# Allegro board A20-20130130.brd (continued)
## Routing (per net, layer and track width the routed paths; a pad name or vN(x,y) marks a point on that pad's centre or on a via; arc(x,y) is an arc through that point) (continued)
SDQ25: length 25.3
  TOP w0.102: U5.C8 84.31,60.26 85.41,60.26 85.51,60.16 85.51,59.07 85.66,58.92 85.88,58.92 86.1,59.15 86.1,60.2 85.9,60.4 85.9,60.61 86.1,60.81 86.1,63.32 86.38,63.59 86.38,63.96 86.14,64.2 85.39,64.2 85.31,64.28 85.31,64.41 85.48,64.57 86.05,64.57 86.11,64.63 86.11,64.99 86.23,65.11 86.4,65.11 86.53,64.98 86.53,64.43 86.61,64.36 86.78,64.36 86.89,64.46 86.89,65.01 86.98,65.11 87.2,65.11 87.31,65 87.31,64.52 87.38,64.44 87.57,64.44 87.72,64.58 87.72,64.99 87.84,65.11 91.04,65.11 95.05,69.11 U1.L1
SDQ26: length 25
  TOP w0.102: U5.D2 78.84,59.06 78.69,59.2 78.69,60.13 78.83,60.27 79.25,60.27 79.25,60.27 79.27,60.27 79.49,60.48 79.49,61.81 79.57,61.9 79.88,61.9 79.97,61.99 79.97,62.09 79.88,62.18 79.47,62.18 79.42,62.23 79.42,62.23 79.42,62.42 79.51,62.51 79.89,62.51 79.97,62.6 79.97,62.7 79.72,62.95 79.72,63.12 79.84,63.25 80,63.25 80.07,63.19 80.23,63.19 80.36,63.31 80.36,63.47 80.29,63.54 80.29,63.7 80.42,63.83 80.58,63.83 80.64,63.76 80.81,63.76 80.93,63.89 80.93,64.05 80.87,64.11 80.87,64.28 81,64.4 81.16,64.4 81.22,64.34 81.39,64.34 81.51,64.47 81.51,64.63 81.45,64.69 81.45,64.86 81.57,64.98 81.74,64.98 81.8,64.92 81.97,64.92 82.09,65.04 82.09,65.21 82.03,65.27 82.03,65.44 82.15,65.56 82.32,65.56 82.38,65.5 82.55,65.5 82.67,65.62 82.67,65.79 82.61,65.85 82.61,66.02 82.73,66.14 82.9,66.14 82.96,66.08 83.13,66.08 83.25,66.2 83.25,66.37 83.19,66.43 83.19,66.6 83.31,66.72 83.48,66.72 83.54,66.66 83.71,66.66 83.83,66.78 83.83,66.95 83.77,67.01 83.77,67.18 83.89,67.3 84.06,67.3 84.12,67.24 84.29,67.24 84.84,67.79 90.72,67.79 91.52,68.6 91.52,68.61 92.65,69.74 U1.H1
SDQ27: length 25.5
  TOP w0.102: U5.C7 83.14,59.82 83.39,59.82 83.49,59.93 83.49,61.74 84.02,62.27 85.73,62.27 85.81,62.34 85.81,62.54 85.73,62.63 84.57,62.63 84.5,62.7 84.5,62.87 84.58,62.95 85.61,62.95 85.69,63.03 85.69,63.19 85.62,63.26 84.96,63.26 84.86,63.36 84.86,63.51 84.98,63.62 85.92,63.62 85.99,63.7 85.99,63.88 85.94,63.93 85.03,63.93 84.95,64.01 84.95,64.46 85.96,65.47 90.97,65.47 94.65,69.14 94.65,70.48 U1.K2
SDQ28: length 25.2
  TOP w0.102: U1.L2 95.45,70.48 95.45,69.08 91.17,64.8 89.5,64.8 89.08,64.37 88.9,64.37 88.51,64.76 88.41,64.76 88.24,64.59 88.24,64.47 88.37,64.33 88.37,64.33 88.62,64.08 88.62,63.92 88.14,63.43 87.97,63.43 87.34,64.06 87.17,64.06 87.05,63.94 87.05,63.77 87.68,63.14 87.68,62.97 87.51,62.8 87.34,62.8 86.8,63.35 86.72,63.35 86.63,63.26 86.63,62.94 86.71,62.86 86.71,59.14 86.05,58.48 85.64,58.48 85.46,58.66 83.48,58.66 83.16,58.34 83.1,58.28 U5.E7
  TOP w0.127: 83.1,58.28 83.08,58.26 ; 95.05,70.88 U1.L2
SDQ29: length 25.1
  TOP w0.102: U1.G2 92.25,70.48 92.25,69.75 91.23,68.72 91.22,68.72 90.59,68.1 84.25,68.1 84.18,68.02 84.18,67.81 84.02,67.65 83.81,67.65 79.24,63.08 79.24,62.93 79.31,62.85 79.31,62.72 78.89,62.3 78.54,62.3 77.5,61.26 77.5,58.83 77.67,58.66 79.24,58.66 79.25,58.65 79.26,58.65 79.65,58.26 79.73,58.26 79.73,58.25 U5.E3
SDQ30: length 25
  TOP w0.102: U1.M1 95.85,69.03 91.32,64.49 89.72,64.49 87.04,61.81 87.04,58.93 87.64,58.34 87.64,57.75 87.51,57.62 86.85,57.62 86.72,57.76 86.72,58.22 86.64,58.3 86.44,58.3 86.37,58.22 86.37,57.9 86.24,57.78 85.82,57.78 85.75,57.7 85.75,57.47 85.83,57.38 86.46,57.38 86.54,57.3 86.54,56.87 86.46,56.79 86.04,56.79 85.69,57.14 85.34,57.14 85.23,57.25 85.23,57.51 85.11,57.62 85.09,57.62 84.85,57.86 84.29,57.86 U5.E8
SDQ31: length 25.1
  TOP w0.102: U1.H2 92.65,70.63 93.04,70.24 93.04,70.23 93.05,70.22 93.05,69.7 90.84,67.49 90.84,67.49 90.8,67.45 85.01,67.45 82.76,65.2 82.76,64.99 82.95,64.8 82.95,64.71 82.84,64.6 82.69,64.6 82.68,64.62 82.68,64.62 82.53,64.77 82.32,64.77 82.21,64.66 82.21,64.49 82.93,63.78 82.93,63.62 82.81,63.5 82.63,63.5 82.32,63.8 81.92,64.2 81.75,64.2 81.64,64.08 81.64,63.93 82.01,63.55 82.01,63.43 81.94,63.36 81.6,63.36 81.38,63.58 81.14,63.58 80.92,63.37 80.92,63.25 80.71,63.03 80.59,63.03 80.31,62.75 80.31,61.25 80.85,60.71 80.85,60.7 81.01,60.55 81.01,60.39 80.81,60.19 80.59,60.19 80.5,60.29 80.5,60.29 80.25,60.54 80.02,60.54 U5.B3
SDQM0: length 26.8
  TOP w0.102: U1.AC6 104.65,74.08 105.28,74.08 106.5,72.86 110.54,72.86 119.55,63.84 119.55,58.86 119.63,58.79 119.88,58.79 120.08,58.99 120.08,60.54 120.17,60.62 120.51,60.62 U2.B7
SDQM1: length 17.6
  TOP w0.102: v1(105.15,62.69) 105.21,62.75 105.35,62.75 105.77,63.17 105.77,64.7 101.83,68.63 101.83,69.22 101.48,69.57 101.48,70.05 U1.W1 ; U3.B7 109.9,60.69 109.87,60.69 109.55,61.01 109.55,62.43 109.97,62.84 v1(109.97,63.25)
  BOTTOM w0.102: v1(105.15,62.69) 105.21,62.76 106.26,62.76 106.76,63.25 v1(109.97,63.25)
SDQM2: length 15.2
  TOP w0.102: U4.B7 93.29,60.77 93.29,61 93.14,61.15 92.49,61.15 92.27,61.37 92.27,61.5 92.36,61.6 92.95,61.6 93.04,61.69 93.04,61.79 92.93,61.9 92.93,62.1 93.11,62.29 93.11,62.29 94.96,64.14 94.96,64.26 96.07,65.36 96.91,65.36 97.03,65.48 97.03,66.32 98.65,67.95 98.65,68.52 98.53,68.64 98.53,68.93 98.65,69.05 98.65,69.26 98.54,69.36 98.54,69.63 98.65,69.73 98.65,70.81 98.6,70.87 98.26,70.87 U1.R2
SDQM3: length 30
  TOP w0.102: U1.G1 91.85,69.78 90.47,68.4 84.11,68.4 77.19,61.48 77.19,58 78.14,57.06 80.07,57.06 82.17,59.16 82.17,59.55 83.08,60.46 83.08,60.64 U5.B7
SDQS0: length 28.2
  TOP w0.114: U2.C3 117.41,59.92 117.78,59.92 117.83,59.87 117.83,59.51 118.15,59.19 118.76,59.19 119.13,59.56 119.13,62.77 117.94,63.96 117.94,64.36 117.46,64.83 116.9,64.83 116.72,65.01 116.72,65.57 116.36,65.93 115.8,65.93 115.63,66.11 115.63,66.66 115.27,67.03 114.71,67.03 114.53,67.2 114.53,67.76 114.17,68.12 113.61,68.12 113.43,68.3 113.43,68.86 113.07,69.22 112.51,69.22 112.34,69.4 112.34,69.95 111.98,70.31 111.42,70.31 111.24,70.49 111.24,71.05 110.88,71.41 110.32,71.41 110.15,71.59 110.15,72.06 109.84,72.36 106.55,72.36 105.32,73.59 104.88,73.59 104.81,73.66 104.27,73.66 U1.AB6
SDQS1: length 18.6
  TOP w0.114: U3.C3 106.76,59.82 106.76,59.67 106.35,59.25 106.35,58.87 106.58,58.64 106.92,58.64 107.71,59.43 107.71,59.48 108.26,60.04 108.26,63.26 108.38,63.38 109.49,63.38 110.08,63.97 110.08,64.8 106.53,68.35 105.19,68.35 103.99,69.55 103.85,69.69 U1.AB1
SDQS2: length 17.7
  TOP w0.114: U4.C3 90.17,59.89 90.17,59.79 89.76,59.38 89.76,59.25 89.76,59.25 89.76,58.95 90.03,58.69 91.55,58.69 91.92,59.06 91.92,59.68 91.24,60.36 91.24,61.09 94.61,64.45 94.61,64.72 98.18,68.29 98.18,70 U1.R1
SDQS3: length 27.6
  TOP w0.114: U1.K1 94.25,69.42 94.06,69.23 94.03,69.23 90.81,66 90.16,66 89.77,66.38 89.35,66.38 89.22,66.25 89.22,66.09 88.94,65.81 88.36,65.81 88.09,66.07 88.09,66.36 87.99,66.46 87.48,66.46 87.36,66.34 87.36,66.19 87,65.84 86.4,65.84 85.93,66.31 85.62,66.31 85.42,66.11 85.42,65.63 85.04,65.25 84.63,65.25 84.45,65.07 84.45,63.36 83.39,62.29 81.55,62.29 81.35,62.09 81.35,61.73 81.55,61.54 82.4,61.54 82.69,61.24 82.69,60.63 81.51,59.43 81.51,59.2 80.98,58.67 79.66,58.67 79.48,58.85 79.48,59.31 79.88,59.71 ; 79.88,59.71 79.9,59.73 U5.C3 ; 79.88,59.71 79.88,59.86
SDQSB0: length 28
  TOP w0.114: U2.D3 117.25,58.96 116.99,58.96 116.91,59.04 116.91,60.01 117.13,60.23 117.92,60.23 118.15,60 118.15,59.64 118.28,59.51 118.63,59.51 118.81,59.69 118.81,62.64 117.62,63.83 117.62,64.22 117.33,64.52 116.77,64.52 116.41,64.88 116.41,65.44 116.23,65.61 115.67,65.61 115.31,65.98 115.31,66.54 115.13,66.71 114.57,66.71 114.21,67.07 114.21,67.63 114.04,67.81 113.48,67.81 113.12,68.17 113.12,68.73 112.94,68.9 112.38,68.9 112.02,69.26 112.02,69.82 111.85,70 111.29,70 110.92,70.36 110.92,70.92 110.75,71.09 110.19,71.09 109.83,71.46 109.83,71.93 109.71,72.05 106.42,72.05 105.19,73.28 U1.AC5
SDQSB1: length 18.6
  TOP w0.114: U3.D3 106.76,59.04 107.14,59.43 107.14,59.43 107.26,59.55 107.26,59.94 107.38,60.06 107.51,60.06 107.59,59.98 107.76,59.98 107.95,60.17 107.95,63.39 108.28,63.73 109.39,63.73 109.76,64.1 109.76,64.67 106.39,68.04 106.06,68.04 105.89,67.87 105.89,67.64 105.79,67.54 105.45,67.54 105.4,67.58 105.4,67.91 105.28,68.04 105.04,68.04 104.5,68.57 103.47,69.61 103.47,70.24 103.47,70.24 103.47,70.78 103.37,70.88 103.06,70.88 U1.AA2
SDQSB2: length 17.6
  TOP w0.114: U1.P2 97.68,70.65 97.87,70.65 97.98,70.53 97.98,70.39 97.86,70.27 97.86,68.43 94.29,64.86 94.29,64.58 90.93,61.22 90.93,60.23 91.61,59.55 91.61,59.19 91.42,59 91.01,59 90.9,59.11 90.9,59.55 90.77,59.68 90.52,59.68 90.18,59.34 U4.D3
SDQSB3: length 27.5
  TOP w0.114: U1.J2 93.45,71.12 93.46,71.13 93.36,71.23 93.24,71.23 93.11,71.11 93.11,70.55 93.19,70.47 93.61,70.47 93.82,70.26 93.82,70.25 93.84,70.24 93.84,69.48 90.67,66.32 90.29,66.32 89.92,66.69 89.21,66.69 88.91,66.38 88.91,66.22 88.81,66.12 88.49,66.12 88.41,66.21 88.41,66.49 88.12,66.78 87.34,66.78 87.04,66.48 87.04,66.33 86.87,66.16 86.53,66.16 86.06,66.63 85.48,66.63 85.1,66.24 85.1,65.76 84.91,65.57 84.5,65.57 84.14,65.21 84.14,63.49 83.26,62.61 81.42,62.61 81.03,62.22 81.03,61.6 81.41,61.22 82.26,61.22 82.38,61.1 82.38,60.77 81.19,59.57 81.19,59.33 80.85,58.99 79.97,58.99 U5.D3
SODT: length 72.3
  TOP w0.102: v1(102.76,64.56) 101.43,63.23 101.43,56.01 v1(101.53,55.91) ; 105.16,56.62 U3.G1 ; 78.11,56.49 78.28,56.65 U5.G1 ; U4.G1 88.57,56.69
  TOP w0.127: U1.AA5 v1(103.45,72.88) ; v1(77.88,56.26) 78.11,56.49
  TOP w0.152: 78.11,56.49 78.28,56.66 ; 88.57,56.69 88.48,56.69 88.26,56.47 v1(88.05,56.47) ; 105.16,56.62 105.04,56.5 104.64,56.5 104.57,56.57 104.57,56.57 v1(104.56,56.58) ; 115.69,56.62 115.7,56.62 115.32,56.24 v1(115.31,56.24) 115.69,56.62
  BOTTOM w0.102: v1(103.45,72.88) 103.72,72.61 103.72,72.54 104.52,71.75 104.52,70.46 106.19,68.79 106.19,63.48 105.79,63.09 104.79,63.09 103.32,64.56 v1(102.76,64.56) ; v1(115.31,56.24) 115.1,56.24 115.04,56.17 113.58,56.17 112.84,55.44 112.84,54.93 112.13,54.22 111.03,54.22 109.9,55.34 108.87,55.34 107.82,56.4 107.58,56.63 105.39,56.63 105.39,56.63 104.62,56.63 104.57,56.58 v1(104.56,56.58) 104.18,56.96 102.26,56.96 101.57,56.27 101.57,55.95 v1(101.53,55.91) 101.53,55.68 100.68,54.84 100.68,54.36 100.29,53.98 92.97,53.98 90.25,56.69 89.58,56.69 89.46,56.81 88.51,56.81 88.17,56.47 v1(88.05,56.47) 87.98,56.4 86.55,56.4 85.95,55.79 85.95,55.56 85.37,54.98 82.23,54.98 80.54,56.68 78.28,56.68 77.88,56.27 v1(77.88,56.26)
SRAS: length 65.4
  TOP w0.102: v1(106.37,57.04) 106.75,57.42 U3.F3 ; v1(80.28,57.86) 80.1,57.68 80.1,57.66 U5.F3 ; U4.F3 90.18,57.46 90.17,57.45 ; v1(117.92,56.44) 117.92,56.81 U2.F3 ; v1(100.26,54.54) 100.26,54.92 100.21,54.97 100.21,63.36 99.53,64.03 v1(99.53,66.13)
  TOP w0.127: U1.T4 v1(99.45,72.08)
  TOP w0.152: v1(89.81,57.09) 90.17,57.45 90.17,57.49
  BOTTOM w0.102: v1(99.45,72.08) 99.06,71.68 99.06,69.49 99.52,69.03 99.52,66.54 99.59,66.48 99.59,66.15 99.56,66.13 v1(99.53,66.13) ; v1(106.37,57.04) 106.34,57.06 ; 106.34,57.06 104.58,57.06 104.33,57.31 102.14,57.31 100.27,55.44 100.27,54.55 v1(100.26,54.54) 100,54.28 93.1,54.28 90.3,57.09 v1(89.81,57.09) 89.61,57.09 89.59,57.11 88.38,57.11 88.12,56.85 87.87,56.85 87.75,56.73 86.43,56.73 85.59,55.89 82.25,55.89 v1(80.28,57.86) ; 106.34,57.06 107.65,57.06 109.01,55.69 110.11,55.69 110.77,55.03 112.01,55.03 112.44,55.46 113.6,56.62 117.74,56.62 v1(117.92,56.44)
SRST: length 105.1
  TOP w0.102: U3.N2 105.96,51.4 105.96,51.4 105.96,50.83 105.88,50.75 105.88,47.37 v1(107.14,46.12) ; U2.N2 116.51,50.36 116.66,50.21 116.66,48.21 116.05,47.6 115.52,47.6 114.79,46.87 114.79,46.81 114.79,46.8 114.79,46.48 114.79,46.48 v1(114.79,46.03) ; v1(82.69,47.38) 82.31,47.38 78.82,50.87 78.82,51.58 U5.N2 ; U4.N2 89.38,51.5 89.37,51.5 89.37,47.84 89.37,47.83 v1(89.37,46.24)
  TOP w0.127: U1.AA6 v1(103.45,73.68)
  BOTTOM w0.102: v1(82.69,47.38) 83.93,46.15 88.91,46.15 88.99,46.24 v1(89.37,46.24) 90.44,45.17 106.23,45.17 107.14,46.08 v1(107.14,46.12) 114.71,46.12 v1(114.79,46.03) 114.88,45.94 118.19,45.94 123.08,50.84 123.08,56.08 116.21,62.96 116.21,62.97 115.34,63.84 107.82,63.84 106.98,64.68 106.98,68.71 104.94,70.75 104.94,71.8 103.93,72.81 103.93,73.2 v1(103.45,73.68)
  BOTTOM w0.152: 82.67,47.38 v1(82.69,47.38)
SWE: length 66.2
  TOP w0.102: v1(89.77,55.49) 90.17,55.89 U4.H3 ; v1(79.48,55.46) 79.88,55.85 U5.H3 ; U3.H3 106.76,55.82 v1(106.36,55.42) ; v1(100.84,52.92) 100.68,53.08 100.68,54.87 100.51,55.04 100.51,63.52 99.94,64.09 v1(99.94,66.71) ; v1(116.9,55.42) 117.3,55.82 U2.H3
  TOP w0.127: U1.T3 v1(99.45,71.28)
  BOTTOM w0.102: v1(99.94,66.71) 99.89,66.76 99.89,69.35 99.45,69.79 v1(99.45,71.28) ; v1(116.9,55.42) 116.51,55.03 115.87,55.03 115.66,55.23 114.48,55.23 114.47,55.22 114.43,55.22 112.51,53.3 110.49,53.3 109.45,54.34 108.48,54.34 107.43,55.38 106.4,55.38 v1(106.36,55.42) 106.15,55.42 105.84,55.11 105.71,55.11 105.65,55.04 105.22,55.04 104.67,55.59 104.46,55.59 103.85,54.97 103.49,54.97 101.44,52.92 v1(100.84,52.92) 100.77,52.85 96.23,52.85 95.76,52.37 94.22,52.37 93.87,52.72 92.88,52.72 90.11,55.49 v1(89.77,55.49) 89.56,55.49 89.19,55.12 88.55,55.12 88.19,55.48 87.36,55.48 86.86,54.98 86.86,54.92 85.36,53.43 83.86,53.43 83.28,54.01 81.73,54.01 80.28,55.46 v1(79.48,55.46)
TP-INT: length 2.8
  TOP w0.102: U1.D3 v1(89.08,71.3)
  BOTTOM w0.102: 87.02,71.72 88.67,71.72 89.08,71.31 v1(89.08,71.3)
TP-WAKEUP: length 12.7
  TOP w0.102: 79.08,85.84 79.08,84.59 85.2,78.46 87.47,78.46 U1.B11
TVDACVCC: length 0.5
  TOP w0.102: U1.W15 v1(101.83,81.65)
TVIN0: length 4.1
  TOP w0.102: U1.AC18 108.8,83.68
TVIN1: length 5.1
  TOP w0.102: 108.8,84.06 104.23,84.06 U1.AB18
TVIN2: length 1.5
  TOP w0.102: U1.AA17 v1(103.43,83.25)
  BOTTOM w0.102: v1(103.43,83.25) 104.42,83.25
TVIN3: length 3.6
  TOP w0.102: U1.Y17 v1(102.63,83.25)
  BOTTOM w0.102: 105.51,82.83 103.03,82.83 102.63,83.24 v1(102.63,83.25)
TWI0-SCK: length 8.4
  TOP w0.102: 81.89,86.83 81.89,85.22 85.83,81.28 U1.A15
TWI0-SDA: length 8.7
  TOP w0.102: 82.27,86.83 82.27,85.37 85.98,81.66 87.47,81.66 U1.B15
TWI1-SCK: length 12.5
  TOP w0.102: 77.48,82.68 84.49,75.68 U1.A8
TWI1-SDA: length 13.2
  TOP w0.102: U1.B8 87.47,76.06 84.58,76.06 77.65,82.98
TWI2-SCK: length 2.2
  TOP w0.102: U1.C8 v1(88.28,75.3)
  BOTTOM w0.102: v1(88.28,75.3) 86.62,75.3
TWI2-SDA: length 2.2
  TOP w0.102: U1.C7 v1(88.28,74.5)
  BOTTOM w0.102: v1(88.28,74.5) 86.62,74.5
TWI3-SCK: length 3.5
  TOP w0.102: U1.A20 86.77,85.28 85.52,86.53 85.52,88.02
TWI3-SDA: length 7.1
  TOP w0.102: 85.82,89.72 85.82,86.73 86.89,85.66 87.47,85.66 U1.B20
  TOP w0.127: 85.82,91.17 85.82,89.72
TWI4-SCK: length 4.5
  TOP w0.102: 84.81,87.74 84.81,86.26 86.59,84.48 U1.A19
TWI4-SDA: length 5.1
  TOP w0.102: U1.B19 87.45,84.88 86.65,84.88 85.16,86.38 85.16,87.97
UART0-RX: length 13.6
  TOP w0.102: 77.34,82.38 84.46,75.26 87.47,75.26 U1.B7
UART0-TX: length 11.3
  TOP w0.102: 78.3,80.94 84.37,74.88 U1.A7
UBOOT: length 0.5
  TOP w0.102: U1.W8 v1(101.83,75.3)
ULVDD: length 0.5
  TOP w0.254: U1.K16 v1(93.88,82.45)
USB0-DRV: length 2.2
  TOP w0.102: U1.C12 v1(88.28,78.5)
  BOTTOM w0.102: v1(88.28,78.5) 86.62,78.5
USB0-IDDET: length 12.9
  TOP w0.102: 77.75,80.08 84.16,73.67 87.45,73.67 U1.B5
USB0-VBUSDET: length 2.2
  TOP w0.102: U1.C5 v1(88.28,72.9)
  BOTTOM w0.102: v1(88.28,72.9) 86.62,72.9
USB1-DRV: length 11.3
  TOP w0.102: 78.16,78.27 83.95,72.48 U1.A4
USB2-DRV: length 10.9
  TOP w0.102: 78.48,78.86 84.07,73.28 U1.A5
USB-ICTRL: length 0.5
  TOP w0.102: U1.G19 v1(91.48,84.85)
UVCC: length 1.1
  TOP w0.254: U1.L16 v1(94.68,82.45) ; U1.L15 v1(94.68,81.65)
VGA-B: length 5.1
  TOP w0.102: 108.8,82.46 104.23,82.46 U1.AB16
VGA-G: length 4.1
  TOP w0.102: U1.AC16 108.8,82.08
VGA-R: length 4.1
  TOP w0.102: U1.AC17 108.8,82.88
VMIC: length 1.6
  TOP w0.102: U1.AA21 v1(103.43,86.45)
  BOTTOM w0.102: v1(103.43,86.45) 104.53,86.45
VRA1: length 7.2
  TOP w0.102: U1.W20 v1(101.83,85.65)
  BOTTOM w0.102: 103.2,89.72 103.2,88.34 102.21,87.35 102.21,85.91 101.96,85.65 v1(101.83,85.65)
  BOTTOM w0.254: 103.2,89.72 103.2,91.66
VRA2: length 6.4
  TOP w0.102: U1.V20 v1(101.03,85.65)
  BOTTOM w0.102: v1(101.03,85.65) 101.04,85.65 101.45,86.06 101.45,88.21 101.88,88.65 101.88,89.72
  BOTTOM w0.254: 101.88,89.72 101.88,91.12
VRN-TVIN: length 2.8
  TOP w0.102: U1.Y16 v1(102.63,82.45)
  BOTTOM w0.102: v1(102.63,82.45) 102.63,82.44 103.04,82.03 104.69,82.03
VRP: length 6.1
  TOP w0.102: U1.W21 v1(101.83,86.45)
  BOTTOM w0.102: 101.83,87.8 v1(101.83,86.45)
  BOTTOM w0.254: 101.83,87.8 102.67,88.64 102.67,91.66
VRP-TVIN: length 1.5
  TOP w0.102: U1.AA16 v1(103.43,82.45)
  BOTTOM w0.102: v1(103.43,82.45) 104.4,82.45
WIFI-PWR: length 2.2
  TOP w0.102: U1.C3 v1(88.28,71.3)
  BOTTOM w0.102: v1(88.28,71.3) 86.62,71.3
WIFI-SHDN-N: length 2.8
  TOP w0.102: U1.D4 v1(89.08,72.1)
  BOTTOM w0.102: 87.02,72.52 88.67,72.52 89.08,72.11 v1(89.08,72.1)
WIFI-WAKEUP: length 11.3
  TOP w0.102: 76.34,73.13 82.35,73.13 82.9,72.58 82.9,72.57 83.65,71.82 83.65,71.82 83.79,71.68 U1.A3
X1: length 8.9
  TOP w0.102: 102.67,89.72 102.67,87.27 102.66,87.26 102.63,87.26 U1.Y22
  TOP w0.127: 102.67,89.72 102.67,95.57
X2: length 8.9
  TOP w0.102: U1.AA22 103.43,87.26 103.46,87.26 103.47,87.27 103.47,89.72
  TOP w0.127: 103.47,89.72 103.47,95.57
Y1: length 7.9
  TOP w0.102: 102.25,89.72 U1.Y23
  TOP w0.127: 102.25,95.57 102.25,89.72
Y2: length 7.9
  TOP w0.102: 103.05,89.72 U1.AA23
  TOP w0.127: 103.05,95.57 103.05,89.72
N22542778: length 0.5
  TOP w0.102: U1.AA7 v1(103.43,74.5)
N23015680: length 0.5
  TOP w0.254: U1.P8 v1(97.83,75.3)
N23015683: length 0.5
  TOP w0.254: U1.R8 v1(98.63,75.3)
N23015686: length 0.5
  TOP w0.254: U1.N8 v1(97.03,75.3)
N23016061: length 0.5
  TOP w0.254: U1.T15 v1(99.43,81.65)
N23188466: length 5.7
  TOP w0.102: U2.H8 121.69,56.2 121.69,56.77 121.92,57 122.93,57 123.64,56.28 124.57,56.28
  TOP w0.127: 124.57,56.28 R4.2
N23197845: length 9.6
  TOP w0.102: R5.2 112.85,48.44 112.85,54.96 112.36,55.45 111.14,55.45 U3.H8
N23198178: length 11.3
  TOP w0.102: R6.2 91.29,47.09 90.88,47.5 90.88,48.87 90.73,49.02 90.73,49.53 91.25,50.06 91.25,52.92 93.04,54.7 93.67,54.7 93.8,54.83 93.8,55.51 U4.H8
N23198522: length 11
  TOP w0.102: U5.H8 84.3,55.46 v1(84.3,55.46)
  TOP w0.127: v1(75.73,58.42) 75.77,58.46 R7.2
  BOTTOM w0.102: 75.85,58.3 76.79,57.37 80.31,57.37 82.22,55.46 v1(84.3,55.46)
  BOTTOM w0.127: v1(75.73,58.42) 75.85,58.3

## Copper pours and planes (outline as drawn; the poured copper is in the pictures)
AGND on GND02: 74.74,77.31 74.74,41.43 129.25,41.43 129.25,77.31
DRAM-VCC on PWR03: 72.7,76.09 72.7,39.1 132.57,39.1 132.57,76.09
